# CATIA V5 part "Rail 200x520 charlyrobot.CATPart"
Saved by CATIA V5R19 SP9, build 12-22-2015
Part number: Rail 200x520 charlyrobot
Bounding box of the stored display mesh (mm): x 0 to 520, y 0 to 40, z 0 to 200
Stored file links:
  Z:\charly_robot\Rail 200x520 charlyrobot.CATPart
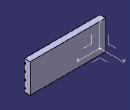
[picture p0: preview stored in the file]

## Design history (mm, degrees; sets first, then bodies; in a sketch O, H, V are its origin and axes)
AxisSystem1: origin (0, 0, 0), X (1, 0, 0), Y (0, 1, 0), Z (0, 0, 1)
Body1 (main body)
  Sketch1 on YZ plane of AxisSystem1, origin (0, 0, 0), H (0, 1, 0), V (0, 0, 1)
    line L1 (0, 0) -> (40, 0)
    line L2 (40, 0) -> (40, 200)
    line L3 (40, 200) -> (0, 200)
    line L4 (0, 200) -> (0, 0)
    distance L4 L2 = 40
    distance L3 L1 = 200
    horizontal: L1 H, L3 H
    vertical: L2 V, L4 V
  Pad1: profile Sketch1, direction (1, 0, 0), length 520
  Sketch2 on YZ plane of AxisSystem1, origin (0, 0, 0), H (0, 1, 0), V (0, 0, 1)
    point P1 (5, 25)
    line L1 (8, 30.1) -> (8, 19.9)
    line L2 (8, 19.9) -> (2, 19.9)
    line L3 (2, 19.9) -> (2, 21.65)
    line L4 (2, 30.1) -> (8, 30.1)
    point P6 (1, 25)
    construction line L5 (5, 21.65) -> (5, 28.35)
    line L6 (2, 28.35) -> (-3, 28.35)
    line L7 (-3, 28.35) -> (-3, 21.65)
    line L8 (-3, 21.65) -> (2, 21.65)
    point P7 (5, 21.65)
    point P8 (5, 28.35)
    reference intersected line E1 through (0, 0) direction (0, 1) from ZX plane of AxisSystem1
    reference intersected line E2 through (0, 0) direction (-1, 0) from XY plane of AxisSystem1
    line L9 (2, 28.35) -> (2, 30.1)
    length L1 = 10.2
    length L4 = 6
    length L7 = 6.7
    distance L3 L7 = 5
    distance L3 E1 = 2
    distance P6 E2 = 25
    vertical: L1 V, L3 V, L5 V, L7 V
    horizontal: L2 H, L4 H, L6 H, L8 H
    equidistance: L1 L3 P1, L2 L4 P1, L5 L7 P6, L6 L8 P6
    midpoint: L5 P1
    coincidence: L3 L9, P7 L8, P8 L6
  Pocket1: profile Sketch2, direction (-1, 0, 0), through (limit type 3)
  Sketch3 on ZX plane of AxisSystem1, origin (0, 0, 0), H (0, 0, 1), V (1, 0, 0)
    construction line L1 (25, 480) -> (25, 520)
    point P2 (25, 520)
    line L2 (19.9, 480) -> (19.9, 520)
    line L3 (30.1, 520) -> (30.1, 480)
    arc A1 centre (25, 520) radius 5.1 from (19.9, 520) to (30.1, 520) cw
    arc A2 centre (25, 480) radius 5.1 from (30.1, 480) to (19.9, 480) cw
    reference intersected line E1 through (0, 0) direction (0, 1) from XY plane of AxisSystem1
    reference intersected line E2 (0, 520) -> (200, 520) from end face of Pad1
    distance L1 L2 = 5.1
    distance L1 E1 = 25
    length L1 = 40
    vertical: L1 V
    tangency: A1 L2, A2 L2, A1 L3, A2 L3
    coincidence: P2 E2
  Pocket2: profile Sketch3, direction (0, 1, 0), length 5
  RectPattern1: of Pocket1, Pocket2, direction 1 instances 4, spacing 50, along Z axis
